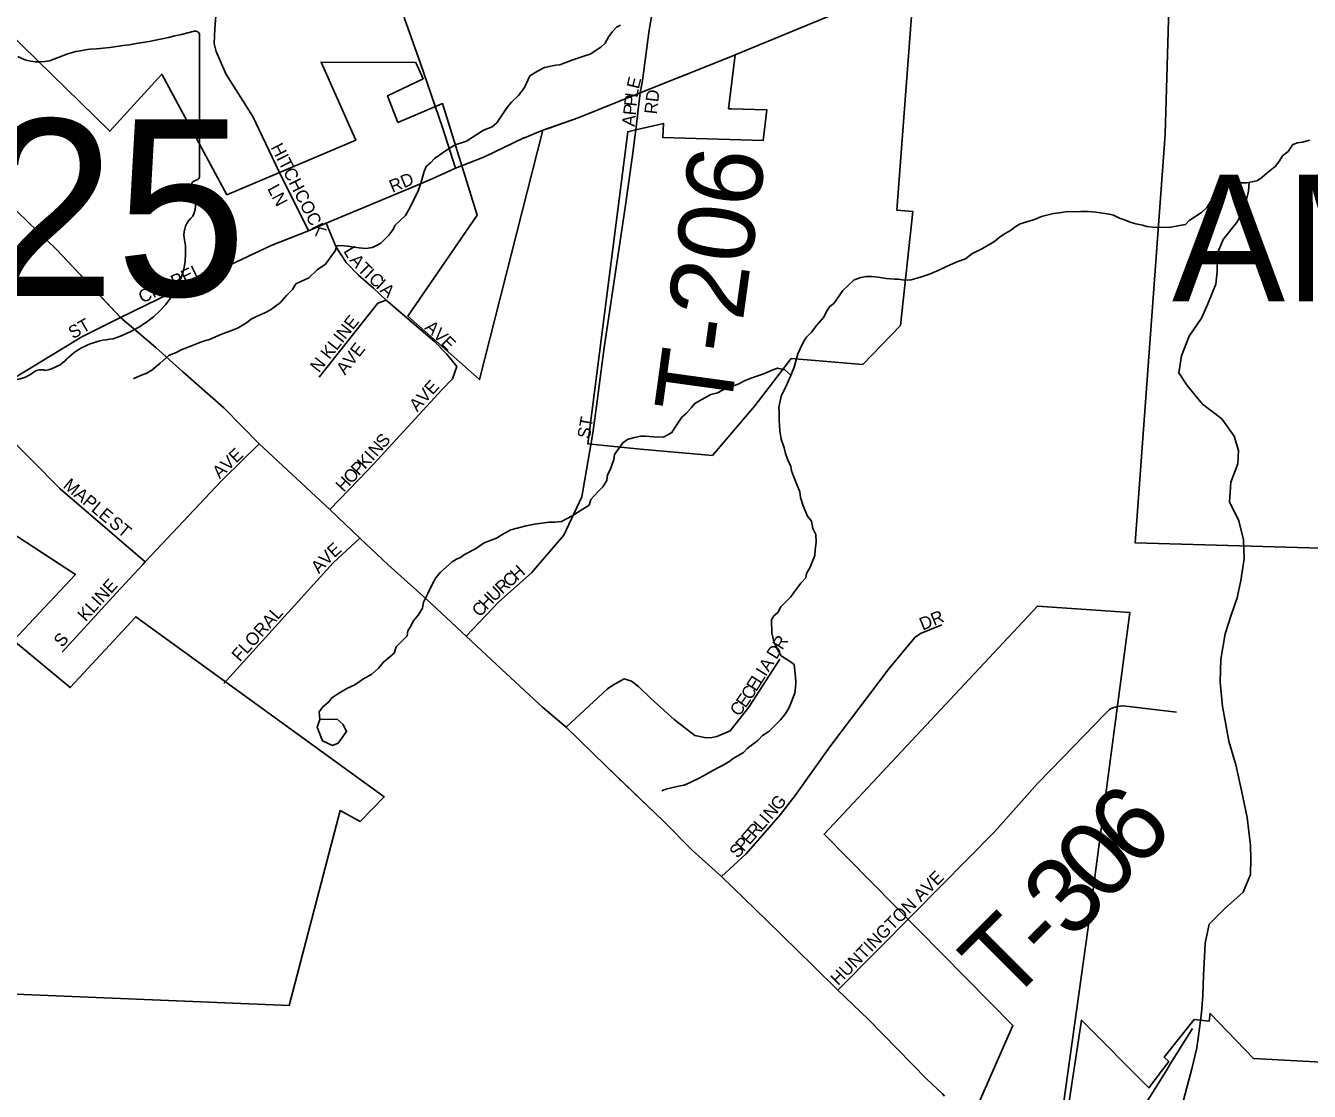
# Model space of a CAD drawing. Extents: x 1310247 to 1664935, y 235267 to 584339.
# Drawn here: x 1479257 to 1484317, y 376865 to 381064 of the extents above; entities that cross this region are included whole.
import ezdxf

# ---------------------------------------------------------------- set-up
doc = ezdxf.new("R2010")
doc.units = 0
for name, color, linetype in [('GM_X_City_Street', 7, 'Continuous'), ('GM_X_City_Street_Text', 7, 'Continuous'), ('GM_X_Corporation', 7, 'Continuous'), ('GM_X_Corporation_Text', 7, 'Continuous'), ('GM_X_County_Road', 7, 'Continuous'), ('GM_X_Minor_River', 7, 'Continuous'), ('GM_X_State_Route', 7, 'Continuous'), ('GM_X_State_Shield', 7, 'Continuous'), ('GM_X_Township', 7, 'Continuous'), ('GM_X_Township_Road', 7, 'Continuous'), ('GM_X_Township_Road_Text', 7, 'Continuous'), ('GM_X_Township_Subdivision', 7, 'Continuous')]:
    doc.layers.add(name, color=color, linetype=linetype)

msp = doc.modelspace()

# ---------------------------------------------------------------- linework, layer by layer
at = {"layer": 'GM_X_City_Street'}
for points in [[(1481658.8, 380624.9), (1481662.3, 380653.8), (1481679.8, 380799), (1481685.6, 380833.3)], [(1479631.8, 379914.8), (1479879.8, 380035.4), (1480225, 380197.8), (1480371.8, 380256.1), (1480442.5, 380286), (1480773.4, 380423.3), (1480862.9, 380461.3), (1480932.1, 380493.3)], [(1480371.8, 380256.1), (1480255.1, 380491)], [(1480956.4, 379721.6), (1480917.1, 379769.8), (1480870.7, 379818), (1480677.9, 379982.2), (1480627.9, 380030.4), (1480569, 380080.4), (1480520.8, 380130.3), (1480481.6, 380191), (1480442.5, 380286)], [(1480413.7, 379678.8), (1480645.9, 379970.1), (1480677.9, 379982.2)], [(1478596.3, 379279.6), (1478601.2, 379279.7), (1478636.9, 379286.5), (1478674, 379311.3), (1478744.1, 379370.1), (1478779.1, 379398.7), (1478813.6, 379428.8), (1478838.3, 379442.9), (1478864.4, 379462.4), (1478934.2, 379508.3), (1479054, 379580.4), (1479478.4, 379838.1), (1479631.8, 379914.8)], [(1480643.6, 379353.1), (1480897.5, 379628.8), (1480939.2, 379672.3), (1480956.4, 379721.6)], [(1479728.2, 378951.3), (1479392.9, 379238.4), (1479054, 379580.4)], [(1480993.9, 378657.7), (1481122.4, 378793.4), (1481251.4, 378908.5), (1481379.1, 379055.8), (1481449.8, 379207), (1481492.9, 379458.3), (1481509.8, 379584.3)], [(1480037.3, 379279), (1480178.1, 379416.4)], [(1480456.6, 379157.5), (1480606.5, 379312.8), (1480643.6, 379353.1)], [(1479633.8, 378848.6), (1479718.7, 378941.1), (1479728.2, 378951.3), (1480027.7, 379269.6), (1480037.3, 379279)], [(1480038.9, 378472.1), (1480469.1, 378946.9), (1480574.4, 379045.1)], [(1479401, 378595), (1479630.2, 378844.7), (1479633.8, 378848.6)], [(1482000.5, 377710.7), (1482097.6, 377800.9), (1482162.1, 377874), (1482230.9, 377954.8), (1482290.4, 378030), (1482426.6, 378221.6), (1482659.4, 378529.3), (1482762.2, 378653.5), (1482784.5, 378669), (1482869.3, 378703.3)], [(1481388.3, 378299.5), (1481551.1, 378450.2), (1481571.4, 378465.8), (1481617.1, 378489.8), (1481645.4, 378481.3), (1481673.6, 378460.1), (1481721.5, 378412.2), (1481813.3, 378330.3), (1481861.2, 378293.6), (1481895.1, 378266.8), (1481939.2, 378257.7), (1481963.2, 378259.2), (1481981.3, 378262.9), (1482034.8, 378285.2), (1482108.2, 378378.3), (1482229.5, 378567.4)], [(1483582.3, 378383.6), (1483583, 378383.7), (1483793.5, 378358.8)], [(1482459.3, 377263.1), (1482758, 377565.7)]]:
    msp.add_lwpolyline(points, dxfattribs=at)
at = {"layer": 'GM_X_Corporation'}
for points in [[(1483768.2, 381313.2), (1483749.5, 380635.9), (1483630.5, 379026.6), (1485367.9, 378976.4)], [(1479185.2, 381042.2), (1479588.5, 380648), (1479793.5, 380873.3), (1480050.3, 380397.8), (1480558.2, 380612.4), (1480421.5, 380920.5), (1480795.5, 380918.9), (1480823.8, 380854.8), (1480683.7, 380788.4), (1480724.8, 380682.8), (1480900.2, 380756.9), (1481036.6, 380317.1), (1480764.3, 379919.8), (1481045.6, 379669.3), (1481296.5, 380651.8), (1481435.6, 380701), (1481679.8, 380799), (1482042, 380944.5), (1482053.5, 380949.3), (1482028.4, 380736.6), (1482038.5, 380736.4), (1482179, 380732.3), (1482164.8, 380612.1), (1481768.3, 380623.6), (1481771.7, 380679.2), (1481662.3, 380653.8), (1481630.5, 380646.4), (1481473.2, 379416.4), (1481680.6, 379395.9), (1481964.4, 379370.4), (1482131.8, 379566.6), (1482275.4, 379753.2), (1482557.7, 379729.3), (1482706, 379882.4), (1482753.8, 380332.3), (1482691.6, 380337), (1482760.1, 381242.5)], [(1477411.6, 377322.4), (1480296.6, 377203), (1480496.8, 377970.8), (1480575.3, 377927.9), (1480670.8, 378024.8), (1479691.4, 378735), (1479433.3, 378455.5), (1479209.8, 378641.8), (1479453.2, 378901.8), (1479002.1, 379195)], [(1483338.7, 376749), (1483444.4, 377501.4), (1483610.2, 378751.7), (1483245.7, 378776.8), (1482404.8, 377877.8), (1483148.2, 377123.5), (1482977.4, 376735.6)], [(1484657.7, 376545.7), (1484705.8, 376961.2), (1484097.7, 376993.5), (1483926.2, 377171.3), (1483922.7, 377141.5), (1483863, 377147.3), (1483745.1, 376999.6), (1483763.1, 376982.2), (1483684.8, 376878.4), (1483419.1, 377144.4), (1483357, 376738.1)]]:
    msp.add_lwpolyline(points, dxfattribs=at)
at = {"layer": 'GM_X_County_Road'}
for points in [[(1481957.2, 380910.5), (1482042, 380944.5), (1482053.5, 380949.3), (1482688.2, 381212.7)], [(1481221, 380621.7), (1481223.3, 380622.8), (1481296.5, 380651.8), (1481321.3, 380660.6), (1481435.7, 380701), (1481679.8, 380799), (1481957.2, 380910.5)], [(1481029.7, 380533), (1481066.3, 380547.3), (1481221, 380621.7)], [(1480932.1, 380493.3), (1480952.2, 380502.7), (1481029.7, 380533)]]:
    msp.add_lwpolyline(points, dxfattribs=at)
at = {"layer": 'GM_X_Minor_River'}
for points in [[(1481602.7, 381066.6), (1481586.5, 381058.9), (1481570.2, 381041.1), (1481555.8, 381021.2), (1481541.3, 380995.4), (1481525, 380979.6), (1481482.3, 380952.2), (1481458.1, 380944.6), (1481413.7, 380929.3), (1481363.2, 380910.1), (1481347.1, 380908.4), (1481302.8, 380899.1), (1481274.5, 380885.6), (1481244, 380866), (1481223.2, 380820.2), (1481200.6, 380788.5), (1481172, 380762.9), (1481159.7, 380747), (1481143.3, 380725.2), (1481130.9, 380705.3), (1481114.5, 380681.5), (1481096.1, 380665.8), (1481061.8, 380652.3), (1481017.1, 380623), (1480994.8, 380609.3), (1480950.4, 380594), (1480930.1, 380582.3), (1480911.8, 380570.6), (1480889.5, 380554.9), (1480869.2, 380541.2), (1480852.9, 380523.5), (1480836.6, 380509.7), (1480828.2, 380489.7), (1480815.4, 380443.8), (1480804.8, 380411.8), (1480786.1, 380376), (1480771.6, 380346.1), (1480755, 380316.3), (1480712.2, 380276.9), (1480705.9, 380260.9), (1480689.5, 380239.1), (1480656.8, 380207.6), (1480640.6, 380197.8), (1480624.4, 380190), (1480598.3, 380186.5), (1480572.2, 380189), (1480552.2, 380191.3), (1480526.2, 380195.8), (1480500.1, 380198.3), (1480484, 380196.5), (1480477.7, 380176.5), (1480438.6, 380125), (1480406.1, 380101.5), (1480373.5, 380069.9), (1480322.9, 380046.7), (1480308.5, 380024.9), (1480286, 380001.2), (1480261.5, 379973.5), (1480222.8, 379944), (1480200.5, 379932.4), (1480170.2, 379918.8), (1480145.9, 379907.2), (1480127.6, 379893.5), (1480095.2, 379874), (1480072.9, 379864.3), (1480026.5, 379847), (1479982, 379827.8), (1479961.8, 379822.1), (1479937.6, 379812.5), (1479891.1, 379795.2), (1479872.9, 379787.5), (1479850.6, 379775.8), (1479822.3, 379764.3), (1479787.7, 379734.8), (1479755.1, 379707.2), (1479732.8, 379693.5)], [(1484319, 380613.2), (1484290.8, 380605.7), (1484270.6, 380602), (1484252.5, 380596.3), (1484233.9, 380568.5), (1484211.6, 380550.8), (1484199.2, 380531), (1484182.8, 380509.2), (1484150.2, 380483.6), (1484129.8, 380465.9), (1484113.6, 380454.1), (1484091.4, 380448.5), (1484069.3, 380444.9), (1484049.2, 380445.2), (1484023.1, 380441.7), (1484006.9, 380438), (1483990.8, 380432.2), (1483964.4, 380416.6), (1483929.6, 380373), (1483913.1, 380347.2), (1483892.7, 380327.5), (1483844, 380296.2), (1483829.6, 380280.4), (1483805.5, 380276.8), (1483765.2, 380269.5), (1483699, 380270.6), (1483677, 380273), (1483659, 380277.4), (1483633, 380283.8), (1483611, 380290.3), (1483589.1, 380298.7), (1483569.1, 380305), (1483545.2, 380317.5), (1483529.2, 380321.8), (1483475.2, 380328.8), (1483447.1, 380331.3), (1483417, 380331.8), (1483354.8, 380330.9), (1483332.6, 380327.3), (1483308.5, 380323.7), (1483262.1, 380312.5)], [(1484080.5, 380446.7), (1484077.7, 380412.3), (1484064.8, 380358.3), (1484033.5, 380292.6), (1483978.1, 380221.4), (1483955.1, 380167.6), (1483953.9, 380095.3), (1483949, 380045.2), (1483917.6, 379967.5), (1483892.5, 379911.7), (1483843.1, 379840.3), (1483813.7, 379762.6), (1483802.5, 379696.5), (1483835.8, 379645.8), (1483896.8, 379572.5), (1483972.1, 379515), (1484021.1, 379445.9), (1484038.2, 379389.4), (1484035.3, 379337.2), (1484008, 379265.5), (1484002.6, 379187.3), (1484039.5, 379112.4), (1484058.3, 379037.8), (1484061, 378963.5), (1484047.5, 378877.4), (1484032.3, 378809.4), (1484009.1, 378741.6), (1483985.7, 378667.7), (1483968, 378567.7), (1483966.4, 378477.4), (1483974.8, 378380.9), (1483987.7, 378310.4), (1484000.6, 378243.9), (1484027.1, 378151.1), (1484049.5, 378050.4), (1484071.8, 377943.6), (1484085.9, 377833), (1484087, 377780.8), (1484086, 377718.6), (1484056.7, 377648.8), (1483983.3, 377583.9), (1483922, 377522.7), (1483906.7, 377448.7), (1483903.8, 377394.6), (1483900.5, 377322.3), (1483897.2, 377242.1), (1483892, 377174), (1483884.9, 377113.9), (1483873.6, 377035.8), (1483854.1, 376953.8), (1483839, 376893.9), (1483815.5, 376810)], [(1483262.1, 380312.5), (1483233.8, 380300.9), (1483177.3, 380283.8), (1483157.1, 380272.1), (1483138.7, 380256.4), (1483118.4, 380244.7), (1483096.1, 380231), (1483075.8, 380213.3), (1483029.1, 380186), (1482986.6, 380164.7), (1482962.2, 380145), (1482931.9, 380135.5), (1482889.4, 380116.1), (1482857.1, 380100.6), (1482820.7, 380085.2), (1482788.4, 380073.8), (1482766.2, 380068.1), (1482748, 380062.4), (1482731.9, 380060.7), (1482713.9, 380063), (1482697.9, 380065.3), (1482681.8, 380065.6), (1482649.8, 380068.1), (1482617.7, 380072.7), (1482591.7, 380075.2), (1482571.6, 380075.5), (1482549.5, 380071.9), (1482523.2, 380062.3), (1482478.4, 380021), (1482443.4, 379969.3), (1482427.1, 379957.6), (1482416.8, 379941.7), (1482402.3, 379913.8), (1482375.7, 379884.2), (1482355.1, 379856.4), (1482334.7, 379836.7), (1482324.4, 379820.8), (1482309.9, 379790.9), (1482301.5, 379771), (1482286.6, 379719), (1482271.9, 379683.1), (1482253.2, 379641.3), (1482236.5, 379607.5), (1482225.7, 379561.4), (1482227.4, 379543.3), (1482226.9, 379509.2), (1482230.2, 379467), (1482235.6, 379434.7), (1482247.1, 379400.4), (1482252.8, 379378.2), (1482260.4, 379356), (1482274, 379327.6), (1482275.7, 379309.5), (1482283.4, 379289.3), (1482308.4, 379226.6), (1482312, 379204.4), (1482321.5, 379172.1), (1482338.9, 379131.7), (1482354.6, 379111.3), (1482360.2, 379083.1), (1482371.8, 379058.8), (1482373.3, 379028.6), (1482368.8, 378998.6), (1482368.4, 378976.5), (1482349.6, 378930.6), (1482335.1, 378904.8), (1482332.8, 378888.8), (1482312.4, 378867), (1482289.8, 378835.3), (1482273.3, 378813.5), (1482234.5, 378774), (1482222.1, 378752.1), (1482205.8, 378738.3), (1482197.5, 378722.4), (1482198.7, 378670.2), (1482202.4, 378654), (1482206.1, 378635.9), (1482213.9, 378619.7), (1482221.6, 378603.5), (1482235.3, 378581.2), (1482253.2, 378568.8), (1482271.1, 378558.4), (1482286.9, 378546.1), (1482292.1, 378497.8), (1482293.8, 378475.7), (1482291.4, 378457.7), (1482289, 378433.6), (1482272.2, 378389.7), (1482263.9, 378371.8), (1482249.5, 378349.9), (1482233.1, 378328.1), (1482210.6, 378306.4), (1482186.1, 378282.8), (1482161.8, 378267.1), (1482143.4, 378247.4), (1482100.7, 378216), (1482086.4, 378200.2), (1482045.8, 378176.8), (1482029.5, 378163), (1481999.1, 378145.5), (1481982.9, 378137.7)], [(1482273.5, 379687), (1482250.3, 379707.7), (1482220.3, 379714.2), (1482200.1, 379706.5), (1482169.7, 379693), (1482151.6, 379687.3), (1482135.4, 379681.5), (1482113.2, 379673.9), (1482093, 379666.2), (1482068.7, 379652.6), (1482006.1, 379629.6), (1481983.8, 379617.9), (1481957.6, 379610.3), (1481911, 379585), (1481894.7, 379575.3), (1481882.4, 379559.4), (1481862, 379537.7), (1481843.7, 379522), (1481814.8, 379478.3), (1481804.5, 379460.4), (1481772.1, 379442.9), (1481731.9, 379443.6), (1481699.9, 379446.1), (1481681.8, 379446.5), (1481657.6, 379440.9), (1481629.4, 379433.3), (1481611.1, 379419.6), (1481578.2, 379374), (1481575.9, 379353.9), (1481561.1, 379314), (1481550.8, 379294.1), (1481548.4, 379272.1), (1481531.9, 379246.2), (1481513.5, 379228.5), (1481484.9, 379196.8), (1481478.5, 379174.9), (1481411.5, 379131.9), (1481369, 379110.5), (1481342.9, 379107), (1481320.8, 379107.3), (1481262.5, 379100.3), (1481230.2, 379092.9), (1481169.7, 379077.9), (1481131.2, 379056.4), (1481113, 379044.7), (1481064.5, 379025.5), (1481030, 379002), (1480987.4, 378980.6), (1480971.2, 378968.9), (1480955, 378961.1), (1480938.8, 378951.4), (1480891.9, 378910), (1480873.5, 378888.2), (1480861, 378864.3), (1480842.3, 378826.5), (1480825.7, 378792.7), (1480821.3, 378768.6), (1480804.8, 378740.8), (1480784.3, 378717.1), (1480775.9, 378697.1), (1480763.6, 378679.3), (1480761.2, 378659.2), (1480718.3, 378615.8), (1480709.9, 378591.8), (1480667.2, 378556.4), (1480648.7, 378532.7), (1480620.2, 378507), (1480589.8, 378491.5), (1480571.5, 378477.8), (1480555.2, 378466), (1480522.9, 378452.5), (1480488.4, 378431), (1480464, 378415.4), (1480451.7, 378399.5), (1480429.3, 378379.8), (1480414.9, 378360), (1480416.4, 378329.9)], [(1479732.8, 379693.5), (1479716.7, 379687.8), (1479684.3, 379674.3), (1479682.3, 379673.1)], [(1480416.4, 378329.9), (1480406, 378300.1), (1480427.1, 378245.6), (1480467, 378226.8), (1480489.2, 378236.5)], [(1480489.2, 378236.5), (1480522.1, 378282.1), (1480508.5, 378310.4), (1480484.8, 378330.9), (1480416.4, 378329.9)], [(1481982.9, 378137.7), (1481956.6, 378124.1), (1481940.4, 378114.3), (1481912, 378098.8), (1481879.7, 378083.3), (1481853.4, 378071.7), (1481837.2, 378068), (1481803, 378060.5), (1481780.8, 378054.9), (1481764.7, 378049.1)]]:
    msp.add_lwpolyline(points, dxfattribs=at)
at = {"layer": 'GM_X_State_Route'}
for points in [[(1477488.7, 382030.9), (1477528.2, 381991.6), (1477754.3, 381771.4), (1477951.1, 381574.6), (1478200.6, 381332.6), (1478307.7, 381225.7), (1478475.3, 381064), (1478660.5, 380878.8), (1478859.2, 380683.9), (1479019.7, 380524.4), (1479149.1, 380403.4), (1479378.6, 380182.2), (1479559.1, 379991.5)], [(1479559.1, 379991.5), (1479631.8, 379914.8), (1479771, 379796.1), (1479877.4, 379700.1), (1480038.1, 379558.2), (1480178.1, 379416.4), (1480456.6, 379157.5), (1480574.4, 379045.1), (1480686.8, 378939.8), (1480836.8, 378804.1), (1480993.9, 378657.7), (1481134.9, 378527.4), (1481294.8, 378378.5), (1481388.3, 378299.5), (1481544.1, 378147.3), (1481592.9, 378100.5)], [(1481592.9, 378100.5), (1481771, 377929.8), (1481886.2, 377813.8), (1482000.5, 377710.7), (1482177.5, 377538.7), (1482362.4, 377357.4), (1482459.3, 377263.1), (1482578.1, 377149.4), (1482810, 376912.6), (1482870.7, 376854.3), (1482879.4, 376845.9)]]:
    msp.add_lwpolyline(points, dxfattribs=at)
at = {"layer": 'GM_X_State_Shield'}
for p, q in [((1479942.9, 380472.7), (1479942.9, 381025.4)), ((1479942.7, 380472.8), (1479942.9, 380472.7))]:
    msp.add_line(p, q, dxfattribs=at)
for centre, major_axis, start_param, end_param in [((1479323, 382439.8), (1845.5, 0), 4.814394, 5.042369), ((1479923.6, 381027.7), (19.4, 0), 6.141152, 7.989035), ((1479558.4, 380676.5), (371.3, 0), 1.699011, 2.107814), ((1479309.2, 381034.2), (141.1, 0), 4.081561, 5.145723), ((1479938.4, 380432.1), (30, 0), 1.883978, 3.671073), ((1479922.2, 380470.6), (20.7, 0), 5.05454, 6.418171), ((1479747.7, 380362.3), (180, 0), 5.934695, 6.695948), ((1480012.3, 380241.4), (130.9, 0), 2.387724, 3.262537), ((1479426.4, 380171.1), (461.6, 0), 5.101752, 6.440018), ((1479621, 379627.8), (252.8, 0), 1.647645, 2.488434), ((1479300.7, 379822), (149.1, 0), 4.937069, 5.64225), ((1479190.1, 379779.1), (141, 0), 4.691044, 5.507374), ((1479317.6, 379676.8), (39.7, 0), 1.147584, 2.315152)]:
    msp.add_ellipse(centre, major_axis=major_axis, ratio=0.8, start_param=start_param, end_param=end_param, dxfattribs=at)
at = {"layer": 'GM_X_Township'}
for points in [[(1482870.7, 376854.3), (1482810, 376912.6), (1482578.1, 377149.4), (1482459.3, 377263.1), (1482362.4, 377357.4), (1482177.6, 377538.7), (1482000.5, 377710.7), (1481886.2, 377813.8), (1481771, 377929.8), (1481544.1, 378147.3), (1481388.3, 378299.6), (1481294.8, 378378.5), (1481134.9, 378527.4), (1480993.9, 378657.7), (1480836.8, 378804.1), (1480686.8, 378939.8), (1480574.4, 379045.1), (1480456.6, 379157.5), (1480178.1, 379416.4), (1480038.1, 379558.2), (1479877.4, 379700.1), (1479771, 379796.1), (1479631.8, 379914.8), (1479378.6, 380182.2), (1479149.1, 380403.4)], [(1479149.1, 380403.4), (1479378.6, 380182.2), (1479631.8, 379914.8), (1479771, 379796.1), (1479877.4, 379700.1), (1480038.1, 379558.2), (1480178.1, 379416.4), (1480456.6, 379157.5), (1480574.4, 379045.1), (1480686.8, 378939.8), (1480836.8, 378804.1), (1480993.9, 378657.7), (1481134.9, 378527.4), (1481294.8, 378378.5), (1481388.3, 378299.6), (1481544.1, 378147.3), (1481771, 377929.8), (1481886.2, 377813.8), (1482000.5, 377710.7), (1482177.6, 377538.7), (1482362.4, 377357.4), (1482459.3, 377263.1), (1482578.1, 377149.4), (1482810, 376912.6), (1482870.7, 376854.3)]]:
    msp.add_lwpolyline(points, dxfattribs=at)
at = {"layer": 'GM_X_Township_Road'}
for points in [[(1481685.6, 380833.3), (1481688.2, 380848.6), (1481714.8, 381046.8), (1481741.5, 381199.4), (1481761.6, 381289.7), (1481779.2, 381412.6), (1481801.7, 381527.9), (1481849.4, 381693.5), (1481907, 381894.1), (1481960.1, 382067.5), (1482108.3, 382556.7), (1482400.3, 383521.1)], [(1480255.1, 380491), (1480152.4, 380705.8), (1480047, 380874.1), (1480024.9, 380923.5), (1480007.8, 380961.9), (1480000.2, 380994.3), (1480002.7, 381051.3), (1480020.6, 381272.9), (1480026.6, 381319.7), (1480030, 381362.3), (1480022.3, 381431.4), (1480020.6, 381443.5)], [(1481509.8, 379584.3), (1481538.1, 379796), (1481618.6, 380338), (1481650, 380552), (1481658.8, 380624.9)], [(1483345.9, 378180.1), (1483510.3, 378349.2), (1483531.3, 378370.3), (1483542.8, 378376), (1483561.1, 378381.6), (1483582.3, 378383.6)], [(1482758, 377565.7), (1483077.1, 377888.8), (1483246.2, 378077.5), (1483345.9, 378180.1)], [(1483761.9, 376960.3), (1483763.7, 376963.2), (1483857.2, 377112.6)], [(1483331.9, 376385.6), (1483508.5, 376610.8), (1483676.5, 376823.7), (1483761.9, 376960.3)]]:
    msp.add_lwpolyline(points, dxfattribs=at)
at = {"layer": 'GM_X_Township_Subdivision'}
msp.add_lwpolyline([(1480952.2, 380502.7), (1480900.8, 380662.7), (1480812.1, 380918.9), (1480750.5, 381092.2), (1480739.9, 381164.8), (1480756.1, 381304.4), (1480851.8, 381955.3)], dxfattribs=at)

# ---------------------------------------------------------------- texts
at = {"layer": 'GM_X_City_Street_Text'}
for s, rotation, p in [('E', 76.2885, (1481673.9, 380812.2)), ('L', 81.6381, (1481669, 380778.6)), ('RD', 83.6518, (1481745.4, 380713.5)), ('P', 83.9524, (1481665.4, 380744.1)), ('A', 83.9567, (1481657.1, 380665.4)), ('P', 83.9495, (1481661.7, 380709.1)), ('HITCHCOCK', 296.8768, (1480222.2, 380585.3)), ('RD', 22.3821, (1480703, 380405)), ('LN', 297.8914, (1480208.5, 380422.5)), ('L', 300.9075, (1480508.2, 380176.1)), ('A', 310.0775, (1480531.4, 380138.8)), ('CHAPEL', 25.6043, (1479717.1, 379969.2)), ('T', 314.7995, (1480562.8, 380101.8)), ('I', 316.9153, (1480589, 380075.4)), ('C', 317.5405, (1480605.5, 380060)), ('I', 317.7017, (1480634.9, 380033.1)), ('A', 318.3166, (1480651.6, 380017.9)), ('ST', 29.7314, (1479443.6, 379828)), ('N KLINE', 51.6659, (1480413.2, 379693.7)), ('A', 317.6749, (1480827.3, 379870.8)), ('V', 316.3444, (1480859.6, 379841.4)), ('AVE', 51.9491, (1480516.1, 379684.6)), ('E', 315.0773, (1480891.3, 379811.2)), ('AVE', 47.7298, (1480800.8, 379540.2)), ('ST', 79.9803, (1481480.5, 379434.1)), ('S', 49.088, (1480669.9, 379396.5)), ('AVE', 43.6692, (1480022.2, 379276.3)), ('N', 48.7808, (1480640.7, 379363.2)), ('P', 46.9323, (1480570.7, 379287.8)), ('K', 46.9323, (1480594.7, 379313.5)), ('I', 47.7216, (1480625.2, 379346.2)), ('O', 46.9323, (1480540.6, 379255.6)), ('MAPLE', 320.195, (1479401.4, 379246.3)), ('H', 46.9323, (1480510.6, 379223.5)), ('ST', 320.1819, (1479581.8, 379096.7)), ('V', 45.4482, (1480443.2, 378934.2)), ('E', 42.3141, (1480473.5, 378965.1)), ('A', 47.3499, (1480413.7, 378902.2)), ('H', 41.767, (1481194.7, 378873.9)), ('KLINE', 47.9128, (1479494, 378713)), ('C', 41.7525, (1481165.2, 378847.5)), ('U', 43.5779, (1481104.1, 378791)), ('R', 41.8554, (1481135.7, 378821.1)), ('C', 46.769, (1481047.3, 378730.7)), ('H', 46.6233, (1481074.4, 378759.5)), ('FLORAL', 48.014, (1480101.2, 378554.6)), ('DR', 22.3775, (1482793, 378680.1)), ('S', 50.1908, (1479401.4, 378611.5)), ('R', 57.92, (1482239.8, 378600.9)), ('D', 57.9093, (1482216.4, 378563.6)), ('I', 57.8991, (1482174.3, 378496.5)), ('A', 57.9093, (1482186, 378515.2)), ('E', 57.8968, (1482136.9, 378436.9)), ('L', 57.8968, (1482155.6, 378466.7)), ('E', 55.1675, (1482094.3, 378372.3)), ('C', 57.8279, (1482115.8, 378403.3)), ('C', 51.6436, (1482067.7, 378338.6)), ('G', 51.5398, (1482227.3, 377967.7)), ('N', 49.5175, (1482197.5, 377932.8)), ('L', 48.7113, (1482159.3, 377889.2)), ('I', 48.7368, (1482182.6, 377915.7)), ('E', 48.7318, (1482110, 377833)), ('R', 48.7504, (1482133.2, 377859.4)), ('S', 48.7318, (1482063.5, 377780.1)), ('P', 48.7517, (1482086.8, 377806.5)), ('HUNTINGTON AVE', 45.3272, (1482459.9, 377278.9))]:
    msp.add_text(s, height=50, rotation=rotation, dxfattribs=at).set_placement(p)
at = {"layer": 'GM_X_Corporation_Text'}
msp.add_text('AMELIA', height=500, rotation=0, dxfattribs=at).set_placement((1483775.9, 379977.7))
at = {"layer": 'GM_X_State_Shield'}
msp.add_text('125', height=696.1, dxfattribs=at).set_placement((1478575.9, 379999))
at = {"layer": 'GM_X_Township_Road_Text'}
for s, rotation, p in [('T-206', 82.1482, (1482032.2, 379521)), ('6', 46.1408, (1483636.3, 377731.1)), ('0', 48.0438, (1483514.5, 377595.6)), ('3', 46.2854, (1483380, 377454.7)), ('T', 45.0212, (1483129.6, 377203.3)), ('-', 45.2547, (1483289.2, 377363))]:
    msp.add_text(s, height=300, rotation=rotation, dxfattribs=at).set_placement(p)

doc.saveas('drawing.dxf')
